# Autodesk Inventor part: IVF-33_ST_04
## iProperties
Created: 2008-10
Part Number: IVF-33_ST_04
Material: 3.3206  AlMgSi 0.5  H22
Document SubType Name: Blech
Designer: Gawin
Density: 2.66 g/cm^3
Mass: 29.3371 g
Surface Area: 114.437 cm^2
Volume: 11.029 cm^3
Stock Number: IVF-33_ST_04
Author: Gawin
